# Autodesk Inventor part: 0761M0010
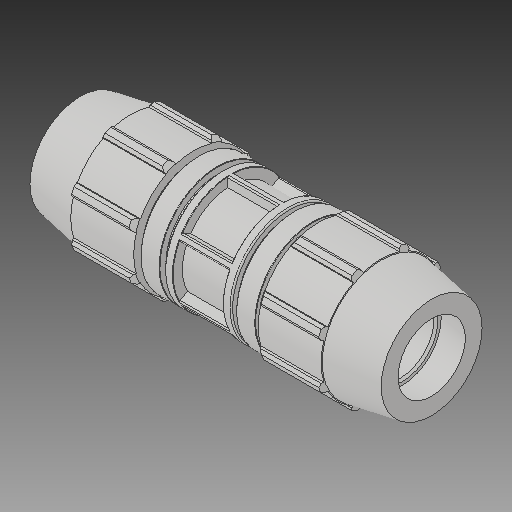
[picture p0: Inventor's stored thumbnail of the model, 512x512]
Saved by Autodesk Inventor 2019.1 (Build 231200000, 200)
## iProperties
Created: 2017-02
Part Number: 0761M0010
Material: Generic
Description: PLASSON REPAIR COUPLER 1'' - 1''
Document SubType Name: Modeling
Designer: KIM
Mass: 2544.89 g
Surface Area: 2949.22 cm^2
Volume: 2544.89 cm^3
Density: 1 g/cm^3
Appearance: Default
Author: KIM
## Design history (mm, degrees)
derived "0761M.ipt"
feature "Solid1::0761M.ipt"
tag "TaggingFeature1"
body "Solid1"
other parameters: "d1" = 173.99, "d2" = 33.3, "d4" = 14.49917, "d5" = 24.85571, "d7" = 64.008, "d8" = 48.006, "d9" = 24.85571, "d11" = 9.35567, "d12" = 51.2064, "d13" = 120 deg, "d14" = 49.95, "d15" = 10 deg, "d16" = 57.6072, "d19" = 35 deg, "d20" = 17.5 deg, "d21" = 59.52744, "d23" = 0, "d25" = 360 deg, "d27" = 1.28016, "d33" = 0.2, "d34" = 3.2004, "d36" = 0, "d37" = 0.666, "d38" = 0.666, "d40" = 360 deg, "d42" = 31.3182, "d43" = 1.92024, "d46" = 0.999, "d50" = 2.44747, "d51" = 51.2064, "d52" = 2.44747, "d_" = 33.3, "E_" = 64.008, "H_" = 173.99, "l_" = 70.104, "d49" = 14.25061
